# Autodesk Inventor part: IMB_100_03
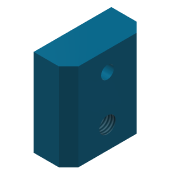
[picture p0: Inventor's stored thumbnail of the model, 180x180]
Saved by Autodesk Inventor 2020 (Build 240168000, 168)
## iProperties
Created: 2011-02
Part Number: IMB_100_03
Document SubType Name: Modeling
Designer: F.Stasiak
Density: 7.73 g/cm^3
Material: Stal, stopowa
Description: Podpora śruby
Appearance: Ciemnobłękitna
Mass: 226.132 g
Surface Area: 71.0864 cm^2
Volume: 29.2538 cm^3
Manager: www.cadconsulting.pl
Company: Fabian Stasiak CAD Consulting
Author: F.Stasiak
Subject: Zbiór ćwiczeń. Autodesk Inventor 2020. Kurs podstawowy
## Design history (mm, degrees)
sketch "Szkic1"
  geometry: L1 (-70, 18)-(-70, -18) reference; L2 (-72, -20)-(-88, -20) reference; L3 (-88, 20)-(-72, 20) reference; L4 (-70, 20)-(-88, 20); L5 (-88, 20)-(-88, -20); L6 (-88, -20)-(-70, -20); L7 (-70, -20)-(-70, 20); 1 further point
  constraints: 8 end point, 3 collinear, 2 parallel, 1 horizontal, 1 perpendicular
extrude "Wyciągnięcie proste1" new body sketch "Szkic1" distance "d0" = 45; taper "d1" = 0 deg
sketch "Szkic2"
  geometry: C1 r 3.324 at (-10, 20) reference; 1 further point
hole "Hole1" sketch "Szkic2" at (-10, 20) diameter "d16" = 6.6; stored, may be unused: countersink angle "d20" = 90 deg, drill point angle "d22" = 118 deg; dims "d17" = 6, "d18" = 11, "d19" = 6.8, "d21" = 8
sketch "Szkic3"
  geometry: C1 r 5.5 at (-33.5, 20) reference; 1 further point
hole "Hole2" sketch "Szkic3" at (-33.5, 20) diameter "d23" = 8.376; stored, may be unused: countersink angle "d27" = 90 deg, drill point angle "d29" = 118 deg; dims "d24" = 6, "d25" = 11, "d26" = 6.8, "d28" = 8
chamfer "Faza5" distance "d30" = 5; stored, may be unused: second distance "d31" = 2, angle "d32" = 45 deg
node "Bryła1"
node "Odniesienie1"
node "Odniesienie2"
node "Odniesienie3"
node "Odniesienie4"
node "Odniesienie5"
